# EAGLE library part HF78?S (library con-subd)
SUB-D
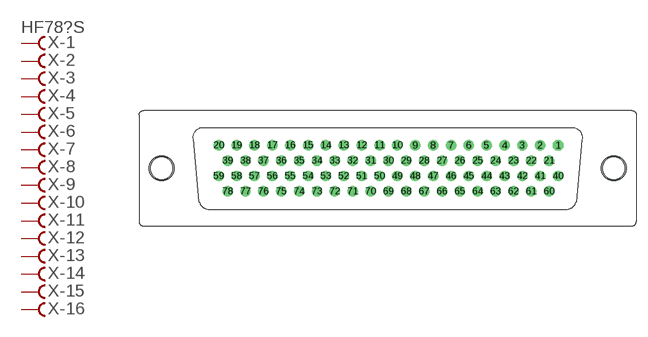
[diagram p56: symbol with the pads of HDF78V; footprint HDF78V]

Designator prefix X; gates -1=FV -2=F -3=F -4=F -5=F -6=F -7=F -8=F -9=F -10=F -11=F -12=F -13=F -14=F -15=F -16=F -17=F -18=F -19=F -20=F -21=F -22=F -23=F -24=F -25=F -26=F -27=F -28=F -29=F -30=F -31=F -32=F -33=F -34=F -35=F -36=F -37=F -38=F -39=F -40=F -41=F -42=F -43=F -44=F -45=F -46=F -47=F -48=F -49=F -50=F -51=F -52=F -53=F -54=F -55=F -56=F -57=F -58=F -59=F -60=F -61=F -62=F -63=F -64=F -65=F -66=F -67=F -68=F -69=F -70=F -71=F -72=F -73=F -74=F -75=F -76=F -77=F -78=F

## HF78VS (OC_FARNELL: unknown; OC_NEWARK: unknown)  [HDF78V]
1  -1:F  pas
2  -2:F  pas
3  -3:F  pas
4  -4:F  pas
5  -5:F  pas
6  -6:F  pas
7  -7:F  pas
8  -8:F  pas
9  -9:F  pas
10  -10:F  pas
11  -11:F  pas
12  -12:F  pas
13  -13:F  pas
14  -14:F  pas
15  -15:F  pas
16  -16:F  pas
17  -17:F  pas
18  -18:F  pas
19  -19:F  pas
20  -20:F  pas
21  -21:F  pas
22  -22:F  pas
23  -23:F  pas
24  -24:F  pas
25  -25:F  pas
26  -26:F  pas
27  -27:F  pas
28  -28:F  pas
29  -29:F  pas
30  -30:F  pas
31  -31:F  pas
32  -32:F  pas
33  -33:F  pas
34  -34:F  pas
35  -35:F  pas
36  -36:F  pas
37  -37:F  pas
38  -38:F  pas
39  -39:F  pas
40  -40:F  pas
41  -41:F  pas
42  -42:F  pas
43  -43:F  pas
44  -44:F  pas
45  -45:F  pas
46  -46:F  pas
47  -47:F  pas
48  -48:F  pas
49  -49:F  pas
50  -50:F  pas
51  -51:F  pas
52  -52:F  pas
53  -53:F  pas
54  -54:F  pas
55  -55:F  pas
56  -56:F  pas
57  -57:F  pas
58  -58:F  pas
59  -59:F  pas
60  -60:F  pas
61  -61:F  pas
62  -62:F  pas
63  -63:F  pas
64  -64:F  pas
65  -65:F  pas
66  -66:F  pas
67  -67:F  pas
68  -68:F  pas
69  -69:F  pas
70  -70:F  pas
71  -71:F  pas
72  -72:F  pas
73  -73:F  pas
74  -74:F  pas
75  -75:F  pas
76  -76:F  pas
77  -77:F  pas
78  -78:F  pas

## Footprint HDF78V (pad centres in mm)
SUB-D
drill 0.9 octagon: 1 23.024,3.12
drill 0.9 round: 2 20.611,3.12; 3 18.198,3.12; 4 15.785,3.12; 5 13.372,3.12; 6 10.959,3.12; 7 8.546,3.12; 8 6.133,3.12; 9 3.72,3.12; 10 1.307,3.12; 11 -1.106,3.12; 12 -3.519,3.12; 13 -5.932,3.12; 14 -8.345,3.12; 15 -10.758,3.12; 16 -13.171,3.12; 17 -15.584,3.12; 18 -17.997,3.12; 19 -20.41,3.12; 20 -22.823,3.12; 21 21.817,1.04; 22 19.404,1.04; 23 16.991,1.04; 24 14.578,1.04; 25 12.165,1.04; 26 9.752,1.04; 27 7.339,1.04; 28 4.926,1.04; 29 2.513,1.04; 30 0.1,1.04; 31 -2.313,1.04; 32 -4.726,1.04; 33 -7.139,1.04; 34 -9.552,1.04; 35 -11.965,1.04; 36 -14.378,1.04; 37 -16.791,1.04; 38 -19.204,1.04; 39 -21.617,1.04; 40 23.024,-1.04; 41 20.611,-1.04; 42 18.198,-1.04; 43 15.785,-1.04; 44 13.372,-1.04; 45 10.959,-1.04; 46 8.546,-1.04; 47 6.133,-1.04; 48 3.72,-1.04; 49 1.307,-1.04; 50 -1.106,-1.04; 51 -3.519,-1.04; 52 -5.932,-1.04; 53 -8.345,-1.04; 54 -10.758,-1.04; 55 -13.171,-1.04; 56 -15.584,-1.04; 57 -17.997,-1.04; 58 -20.41,-1.04; 59 -22.823,-1.04; 60 21.817,-3.12; 61 19.404,-3.12; 62 16.991,-3.12; 63 14.578,-3.12; 64 12.165,-3.12; 65 9.752,-3.12; 66 7.339,-3.12; 67 4.926,-3.12; 68 2.513,-3.12; 69 0.1,-3.12; 70 -2.313,-3.12; 71 -4.726,-3.12; 72 -7.139,-3.12; 73 -9.552,-3.12; 74 -11.965,-3.12; 75 -14.378,-3.12; 76 -16.791,-3.12; 77 -19.204,-3.12; 78 -21.617,-3.12
hole 3 at -30.55,0
hole 3 at 30.55,0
